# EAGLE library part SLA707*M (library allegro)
UNIPOLAR STEPPER-MOTOR TRANSLATOR/DRIVERS Output current: SLA7070M = 1.0 A, SLA7071M = 1.5 A, SLA7072M = 2.0 A, SLA7073M = 3.0 A Source: 2821003.pdf / 970701.pdf http://www.allegromicro.com/en/Products/Part_Numbers/970701/970702.pdf
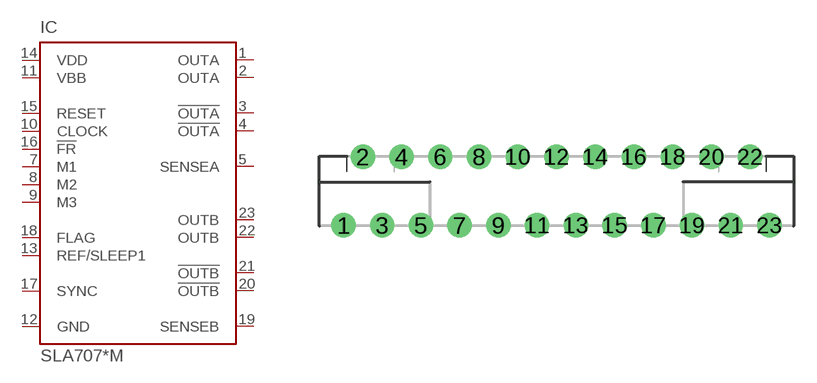
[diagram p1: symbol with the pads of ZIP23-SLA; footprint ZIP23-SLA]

Designator prefix IC

## SLA7070M (MPN: SLA7070MR; OC_FARNELL: unknown; OC_NEWARK: 87K4943), SLA7071M (MPN: SLA7071MR; OC_FARNELL: unknown; OC_NEWARK: 87K4945), SLA7072M (MPN: SLA7072MR; OC_FARNELL: unknown; OC_NEWARK: 87K4947), SLA7073M (MPN: SLA7073MR; OC_FARNELL: unknown; OC_NEWARK: 87K4949), SLA7075M (MPN: SLA7075MR; OC_FARNELL: unknown; OC_NEWARK: 87K4951), SLA7076M (MPN: SLA7076MR; OC_FARNELL: unknown; OC_NEWARK: 87K4953), SLA7077M (MPN: SLA7077MR; OC_FARNELL: unknown; OC_NEWARK: 87K4955), SLA7078M (MPN: SLA7078MR; OC_FARNELL: unknown; OC_NEWARK: 87K4957)  [ZIP23-SLA]
1  OUTA  out
2  OUTA  out
3  !OUTA  out
4  !OUTA  out
5  SENSEA  in
6  NC  nc
7  M1  in
8  M2  in
9  M3  in
10  CLOCK  in
11  VBB  pwr
12  GND  pwr
13  REF/SLEEP1  pwr
14  VDD  pwr
15  RESET  in
16  !FR  in
17  SYNC  in
18  FLAG  in
19  SENSEB  in
20  !OUTB  out
21  !OUTB  out
22  OUTB  out
23  OUTB  out

## Footprint ZIP23-SLA (pad centres in mm)
Small molded power package ZIP-type 23-pin SLA package Source: 2821003.pdf
drill 0.8 pad 1.6 round: 1 -13.97,-2.25; 2 -12.7,2.25; 3 -11.43,-2.25; 4 -10.16,2.25; 5 -8.89,-2.25; 6 -7.62,2.25; 7 -6.35,-2.25; 8 -5.08,2.25; 9 -3.81,-2.25; 10 -2.54,2.25; 11 -1.27,-2.25; 12 0,2.25; 13 1.27,-2.25; 14 2.54,2.25; 15 3.81,-2.25; 16 5.08,2.25; 17 6.35,-2.25; 18 7.62,2.25; 19 8.89,-2.25; 20 10.16,2.25; 21 11.43,-2.25; 22 12.7,2.25; 23 13.97,-2.25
